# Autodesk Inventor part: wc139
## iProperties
Shininess: 64.0
Length Units: 11272
Angle Units: 11279
Time Units: 11290
Mass Units: 11286
Length Display Precision: 3
Angle Display Precision: 2
Compacted: True
Part Number: wc139
Document SubType Name: Modeling
Created: 2004-08
Designer: John Blackburn
Manufacturer: Standard
Standards Organization: Custom
Density: 0.0
Volumn: 0.0
Area: 0.0
PropertySet Name: Model Information
Control State: 0
Master: False
Checked Out: False
Author: John Blackburn
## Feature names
1. Base1
